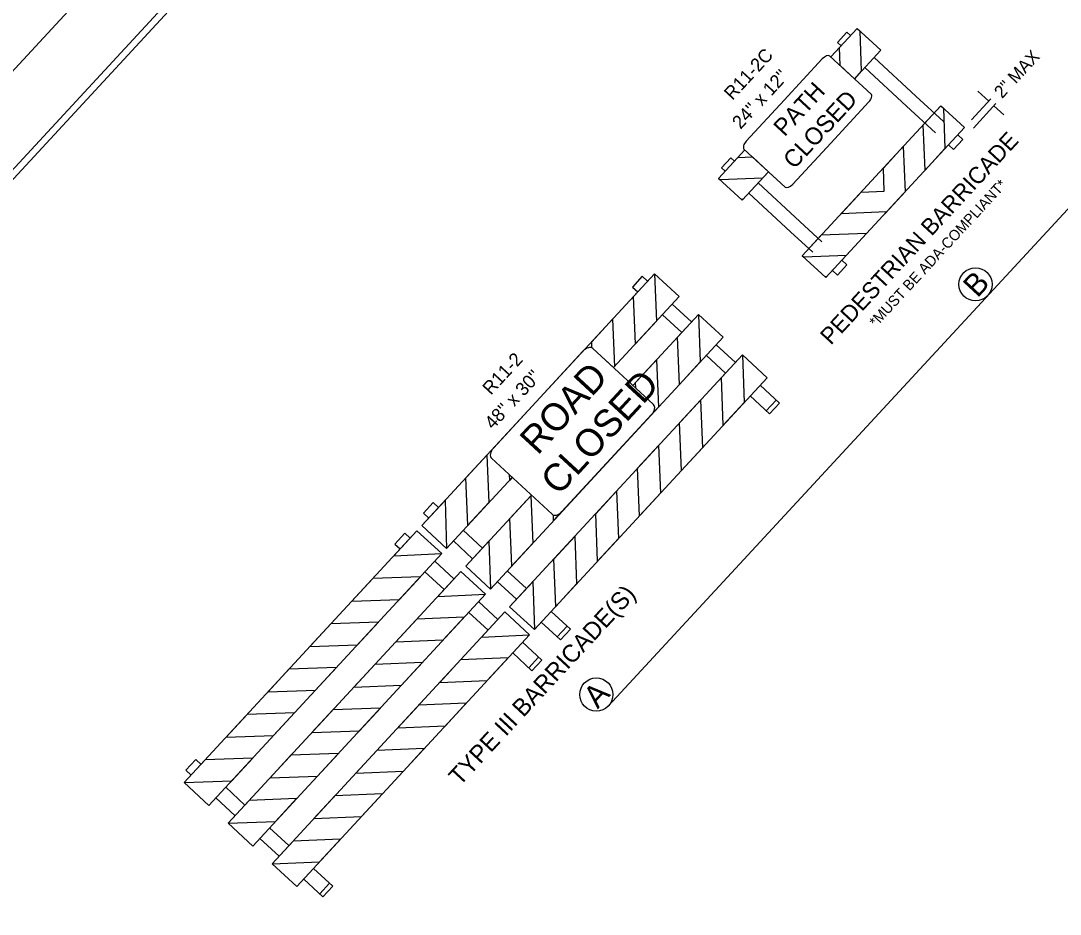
# Model space of a CAD drawing. Extents: x 1767460 to 1770129, y 996106 to 1001438.
# Drawn here: x 1768388.3 to 1768857.4, y 1000227.2 to 1000630.4 of the extents above; entities that cross this region are included whole.
import ezdxf

# ---------------------------------------------------------------- set-up
doc = ezdxf.new("R2010")
doc.units = 0
for name, color, linetype in [('_CIVIL_CONSTRUCTION', 7, 'Continuous'), ('E_NCDOT_Terrain_Model_Contour_Minor', 7, 'Continuous'), ('E_NCDOT_Terrain_Model_Points_Low', 7, 'Continuous'), ('E_NCDOT_Terrain_Model_Triangle_Vertices', 7, 'Continuous'), ('P_NCDOT_Terrain_Flow_Arrows', 7, 'Continuous'), ('P_NCDOT_Terrain_Points_High', 7, 'Continuous'), ('P_NCDOT_Terrain_Points_Low', 7, 'Continuous'), ('P_NCDOT_Terrain_Void', 7, 'Continuous'), ('P_RDY_Slope_Stake_Fill_Limits', 7, 'Continuous')]:
    doc.layers.add(name, color=color, linetype=linetype)

msp = doc.modelspace()

# ---------------------------------------------------------------- linework, layer by layer
at = {"layer": '_CIVIL_CONSTRUCTION'}
for centre in [(1768819.17, 1000511.43), (1768648.04, 1000326.3)]:
    msp.add_circle(centre, 7.5, dxfattribs=at)
at = {"layer": 'E_NCDOT_Terrain_Model_Contour_Minor'}
msp.add_lwpolyline([(1768744.05, 999038.07), (1770128.77, 1000536.12), (1769152.55, 1001438.49), (1767767.83, 999940.44)], close=True, dxfattribs=at)
at = {"layer": 'E_NCDOT_Terrain_Model_Points_Low'}
msp.add_lwpolyline([(1767804.38, 999935.46), (1769171.05, 1001413.98), (1770107.33, 1000548.53), (1768740.66, 999070.01)], close=True, dxfattribs=at)
at = {"layer": 'E_NCDOT_Terrain_Model_Triangle_Vertices'}
msp.add_lwpolyline([(1769163.02, 1001400.87), (1767932.52, 1000069.67), (1768864.37, 999208.32), (1770094.87, 1000539.52)], close=True, dxfattribs=at)
at = {"layer": 'P_NCDOT_Terrain_Flow_Arrows'}
for p, q in [((1768770.98, 1000593.73), (1768753.85, 1000575.19)), ((1768753.85, 1000575.19), (1768736.71, 1000556.65))]:
    msp.add_line(p, q, dxfattribs=at)
for points in [[(1768753.48, 1000614.44), (1768772.02, 1000597.31)], [(1768732.86, 1000594.59), (1768750, 1000613.13)], [(1768715.73, 1000576.05), (1768732.86, 1000594.59)], [(1768733.23, 1000555.34), (1768714.69, 1000572.47)]]:
    msp.add_lwpolyline(points, dxfattribs=at)
for centre, major_axis, start_param, end_param in [((1768751.22, 1000611.99), (2.26, 2.45), 0, 1.570796), ((1768769.76, 1000594.86), (-2.26, -2.45), 1.570796, 3.141593), ((1768716.95, 1000574.92), (-2.26, -2.45), 4.712162, 6.283185), ((1768735.49, 1000557.79), (-2.26, -2.45), 0, 1.570796)]:
    msp.add_ellipse(centre, major_axis=major_axis, ratio=0.5, start_param=start_param, end_param=end_param, dxfattribs=at)
at = {"layer": 'P_NCDOT_Terrain_Points_High'}
msp.add_lwpolyline([(1769163.02, 1001400.87), (1767932.52, 1000069.67), (1768864.37, 999208.32), (1769639.43, 1000046.81), (1769513.61, 1000163.11), (1769964.83, 1000651.25), (1769968.19, 1000656.62)], close=True, dxfattribs=at)
at = {"layer": 'P_NCDOT_Terrain_Points_Low'}
for p, q in [((1768765.78, 1000626.89), (1768753.91, 1000614.05)), ((1768761.16, 1000625.2), (1768756.91, 1000620.6)), ((1768757.83, 1000618.28), (1768765.78, 1000626.89)), ((1768762.81, 1000623.67), (1768761.11, 1000625.24)), ((1768776.39, 1000617.08), (1768765.78, 1000626.89)), ((1768758.56, 1000619.08), (1768756.91, 1000620.6)), ((1768758.15, 1000610.13), (1768757.83, 1000618.28)), ((1768764.52, 1000604.24), (1768776.39, 1000617.08)), ((1768792.3, 1000596.41), (1768773.42, 1000613.86)), ((1768788.06, 1000591.81), (1768769.17, 1000609.27)), ((1768804.7, 1000584.95), (1768792.3, 1000596.41)), ((1768817.4, 1000585.67), (1768826.1, 1000595.09)), ((1768820.28, 1000598.67), (1768825.2, 1000594.12)), ((1768803.55, 1000591.98), (1768741.01, 1000524.33)), ((1768801.1, 1000579.75), (1768788.06, 1000591.81)), ((1768795.59, 1000583.37), (1768803.55, 1000591.98)), ((1768814.16, 1000582.17), (1768803.55, 1000591.98)), ((1768818.23, 1000581.97), (1768828.4, 1000592.97)), ((1768827.5, 1000591.99), (1768831.95, 1000587.88)), ((1768751.63, 1000514.52), (1768814.16, 1000582.17)), ((1768796.4, 1000562.95), (1768795.59, 1000583.37)), ((1768813.48, 1000576.83), (1768809.24, 1000572.23)), ((1768813.48, 1000576.83), (1768811.19, 1000578.95)), ((1768715.12, 1000572.08), (1768703.25, 1000559.24)), ((1768777.59, 1000563.9), (1768786.59, 1000573.64)), ((1768786.59, 1000573.64), (1768787.39, 1000553.21)), ((1768805.4, 1000572.69), (1768796.4, 1000562.95)), ((1768809.24, 1000572.23), (1768806.94, 1000574.36)), ((1768711.8, 1000568.48), (1768703.25, 1000559.24)), ((1768708.81, 1000568.57), (1768704.57, 1000563.98)), ((1768710.47, 1000567.05), (1768708.81, 1000568.57)), ((1768718.71, 1000568.75), (1768711.8, 1000568.48)), ((1768706.22, 1000562.45), (1768704.57, 1000563.98)), ((1768713.86, 1000549.43), (1768725.73, 1000562.27)), ((1768778, 1000553.46), (1768777.59, 1000563.9)), ((1768703.25, 1000559.24), (1768713.86, 1000549.43)), ((1768739.96, 1000539.78), (1768721.08, 1000557.24)), ((1768735.72, 1000535.19), (1768716.83, 1000552.64)), ((1768758.56, 1000543.31), (1768767.57, 1000553.05)), ((1768767.57, 1000553.05), (1768778, 1000553.46)), ((1768787.39, 1000553.21), (1768778.39, 1000543.47)), ((1768714.21, 1000549.8), (1768713.48, 1000549.78)), ((1768713.86, 1000549.43), (1768714.21, 1000549.8)), ((1768778.99, 1000544.12), (1768758.56, 1000543.31)), ((1768749.88, 1000530.62), (1768739.96, 1000539.78)), ((1768745.69, 1000525.96), (1768735.72, 1000535.19)), ((1768769.98, 1000534.38), (1768749.56, 1000533.57)), ((1768760.98, 1000524.64), (1768769.98, 1000534.38)), ((1768749.56, 1000533.57), (1768741.01, 1000524.33)), ((1768741.01, 1000524.33), (1768751.63, 1000514.52)), ((1768761.14, 1000520.2), (1768756.9, 1000515.61)), ((1768761.14, 1000520.2), (1768758.85, 1000522.33)), ((1768751.98, 1000514.9), (1768751.25, 1000514.87)), ((1768751.63, 1000514.52), (1768751.98, 1000514.9)), ((1768756.9, 1000515.61), (1768754.6, 1000517.73))]:
    msp.add_line(p, q, dxfattribs=at)
for points in [[(1768765.78, 1000626.89), (1768766.92, 1000625.83), (1768767.64, 1000607.6)], [(1768767.64, 1000607.6), (1768764.52, 1000604.24), (1768758.15, 1000610.13)], [(1768803.55, 1000591.98), (1768804.68, 1000590.93), (1768805.4, 1000572.69)], [(1768723.21, 1000559.54), (1768725.73, 1000562.27), (1768718.71, 1000568.75)], [(1768703.25, 1000559.24), (1768703.74, 1000558.78), (1768723.21, 1000559.54)], [(1768741.01, 1000524.33), (1768741.51, 1000523.87), (1768760.98, 1000524.64)]]:
    msp.add_lwpolyline(points, dxfattribs=at)
at = {"layer": 'P_NCDOT_Terrain_Void'}
msp.add_line((1768653.55, 1000321.21), (1769189.14, 1000900.63), dxfattribs=at)
at = {"layer": 'P_RDY_Slope_Stake_Fill_Limits'}
for p, q in [((1768569.28, 1000402.55), (1768674.32, 1000516.19)), ((1768668.78, 1000515.04), (1768664.32, 1000510.22)), ((1768664.86, 1000505.96), (1768674.32, 1000516.19)), ((1768668.78, 1000515.04), (1768671.19, 1000512.81)), ((1768674.32, 1000516.19), (1768685.46, 1000505.89)), ((1768674.32, 1000516.19), (1768675.16, 1000494.75)), ((1768664.32, 1000510.22), (1768666.74, 1000507.99)), ((1768685.46, 1000505.89), (1768655.84, 1000473.84)), ((1768665.71, 1000484.52), (1768664.86, 1000505.96)), ((1768682.34, 1000502.51), (1768691.02, 1000494.49)), ((1768664.52, 1000465.82), (1768694.14, 1000497.86)), ((1768677.88, 1000497.69), (1768686.56, 1000489.66)), ((1768684.69, 1000487.64), (1768694.14, 1000497.86)), ((1768694.14, 1000497.86), (1768705.28, 1000487.57)), ((1768694.14, 1000497.86), (1768694.98, 1000476.42)), ((1768645.96, 1000485.51), (1768655.41, 1000495.74)), ((1768655.41, 1000495.74), (1768656.25, 1000474.3)), ((1768675.16, 1000494.75), (1768665.71, 1000484.52)), ((1768705.28, 1000487.57), (1768600.24, 1000373.93)), ((1768685.53, 1000466.2), (1768684.69, 1000487.64)), ((1768646.07, 1000482.76), (1768645.96, 1000485.51)), ((1768655.84, 1000473.84), (1768646.5, 1000482.47)), ((1768702.16, 1000484.19), (1768710.84, 1000476.16)), ((1768608.92, 1000365.91), (1768713.96, 1000479.54)), ((1768665.78, 1000467.19), (1768675.24, 1000477.41)), ((1768675.24, 1000477.41), (1768676.08, 1000455.97)), ((1768697.7, 1000479.37), (1768706.38, 1000471.34)), ((1768704.51, 1000469.32), (1768713.96, 1000479.54)), ((1768713.96, 1000479.54), (1768714.8, 1000458.1)), ((1768713.96, 1000479.54), (1768725.1, 1000469.24)), ((1768656.25, 1000474.3), (1768655.84, 1000473.84)), ((1768694.98, 1000476.42), (1768685.53, 1000466.2)), ((1768725.1, 1000469.24), (1768620.07, 1000355.61)), ((1768705.35, 1000447.88), (1768704.51, 1000469.32)), ((1768665.89, 1000464.55), (1768665.78, 1000467.19)), ((1768673.85, 1000457.19), (1768665.89, 1000464.55)), ((1768721.98, 1000465.87), (1768730.66, 1000457.84)), ((1768685.61, 1000448.87), (1768695.06, 1000459.09)), ((1768695.06, 1000459.09), (1768695.9, 1000437.65)), ((1768717.52, 1000461.04), (1768726.21, 1000453.02)), ((1768729.22, 1000459.18), (1768724.76, 1000454.36)), ((1768676.08, 1000455.97), (1768673, 1000452.65)), ((1768714.8, 1000458.1), (1768705.35, 1000447.88)), ((1768730.66, 1000457.84), (1768726.21, 1000453.02)), ((1768672.99, 1000452.63), (1768632.54, 1000408.87)), ((1768686.45, 1000427.43), (1768685.61, 1000448.87)), ((1768666.7, 1000428.42), (1768676.16, 1000438.64)), ((1768676.16, 1000438.64), (1768677, 1000417.2)), ((1768695.9, 1000437.65), (1768686.45, 1000427.43)), ((1768589.21, 1000424.11), (1768598.66, 1000434.34)), ((1768598.66, 1000434.34), (1768599.5, 1000412.9)), ((1768667.55, 1000406.98), (1768666.7, 1000428.42)), ((1768610.04, 1000424.3), (1768580.42, 1000392.26)), ((1768590.05, 1000402.67), (1768589.21, 1000424.11)), ((1768608.95, 1000423.12), (1768608.86, 1000425.39)), ((1768608.86, 1000425.39), (1768610.04, 1000424.3)), ((1768610.04, 1000424.3), (1768608.95, 1000423.12)), ((1768647.76, 1000407.92), (1768657.21, 1000418.14)), ((1768657.21, 1000418.14), (1768658.05, 1000396.7)), ((1768677, 1000417.2), (1768667.55, 1000406.98)), ((1768569.28, 1000402.55), (1768579.76, 1000413.89)), ((1768574.45, 1000412.98), (1768569.99, 1000408.16)), ((1768574.45, 1000412.98), (1768576.86, 1000410.75)), ((1768579.76, 1000413.89), (1768580.42, 1000392.26)), ((1768589.1, 1000384.23), (1768618.72, 1000416.28)), ((1768599.5, 1000412.9), (1768590.05, 1000402.67)), ((1768609.03, 1000405.79), (1768618.48, 1000416.02)), ((1768618.48, 1000416.02), (1768619.32, 1000394.58)), ((1768569.99, 1000408.16), (1768572.4, 1000405.93)), ((1768628.78, 1000404.8), (1768628.68, 1000407.29)), ((1768632.53, 1000408.87), (1768628.78, 1000404.8)), ((1768648.6, 1000386.48), (1768647.76, 1000407.92)), ((1768580.42, 1000392.26), (1768569.28, 1000402.55)), ((1768580.42, 1000392.26), (1768569.28, 1000402.55)), ((1768609.87, 1000384.35), (1768609.03, 1000405.79)), ((1768567.11, 1000400.21), (1768462.07, 1000286.57)), ((1768567.11, 1000400.21), (1768556.63, 1000388.87)), ((1768557.12, 1000394.24), (1768561.57, 1000399.06)), ((1768561.57, 1000399.06), (1768563.99, 1000396.83)), ((1768578.25, 1000389.91), (1768567.11, 1000400.21)), ((1768578.25, 1000389.91), (1768567.11, 1000400.21)), ((1768588, 1000400.46), (1768596.68, 1000392.43)), ((1768628.85, 1000387.47), (1768638.3, 1000397.69)), ((1768638.3, 1000397.69), (1768639.15, 1000376.25)), ((1768557.12, 1000394.24), (1768559.53, 1000392.01)), ((1768583.54, 1000395.63), (1768592.22, 1000387.61)), ((1768589.1, 1000384.23), (1768599.58, 1000395.57)), ((1768599.58, 1000395.57), (1768600.24, 1000373.93)), ((1768619.32, 1000394.58), (1768609.87, 1000384.35)), ((1768658.05, 1000396.7), (1768648.6, 1000386.48)), ((1768473.21, 1000276.27), (1768578.25, 1000389.91)), ((1768556.63, 1000388.87), (1768578.25, 1000389.91)), ((1768575.13, 1000386.53), (1768583.81, 1000378.51)), ((1768600.24, 1000373.93), (1768589.1, 1000384.23)), ((1768600.24, 1000373.93), (1768589.1, 1000384.23)), ((1768629.7, 1000366.03), (1768628.85, 1000387.47)), ((1768586.93, 1000381.88), (1768481.89, 1000268.25)), ((1768568.62, 1000379.49), (1768547.18, 1000378.65)), ((1768559.17, 1000369.26), (1768568.62, 1000379.49)), ((1768570.67, 1000381.71), (1768579.35, 1000373.68)), ((1768586.93, 1000381.88), (1768576.45, 1000370.55)), ((1768598.07, 1000371.58), (1768586.93, 1000381.88)), ((1768598.07, 1000371.58), (1768586.93, 1000381.88)), ((1768607.82, 1000382.13), (1768616.5, 1000374.11)), ((1768547.18, 1000378.65), (1768537.73, 1000368.42)), ((1768603.36, 1000377.31), (1768612.05, 1000369.28)), ((1768608.92, 1000365.91), (1768619.4, 1000377.24)), ((1768619.4, 1000377.24), (1768620.07, 1000355.61)), ((1768639.15, 1000376.25), (1768629.7, 1000366.03)), ((1768493.04, 1000257.95), (1768598.07, 1000371.58)), ((1768576.45, 1000370.55), (1768598.07, 1000371.58)), ((1768537.73, 1000368.42), (1768559.17, 1000369.26)), ((1768594.95, 1000368.21), (1768603.63, 1000360.18)), ((1768620.07, 1000355.61), (1768608.92, 1000365.91)), ((1768620.07, 1000355.61), (1768608.92, 1000365.91)), ((1768606.75, 1000363.56), (1768501.72, 1000249.93)), ((1768567, 1000360.32), (1768557.55, 1000350.1)), ((1768588.44, 1000361.17), (1768567, 1000360.32)), ((1768578.99, 1000350.94), (1768588.44, 1000361.17)), ((1768590.49, 1000363.38), (1768599.17, 1000355.36)), ((1768606.75, 1000363.56), (1768596.28, 1000352.22)), ((1768617.89, 1000353.26), (1768606.75, 1000363.56)), ((1768617.89, 1000353.26), (1768606.75, 1000363.56)), ((1768627.64, 1000363.81), (1768636.33, 1000355.78)), ((1768528.28, 1000358.2), (1768518.82, 1000347.97)), ((1768549.72, 1000359.04), (1768528.28, 1000358.2)), ((1768540.26, 1000348.81), (1768549.72, 1000359.04)), ((1768623.19, 1000358.99), (1768631.87, 1000350.96)), ((1768634.88, 1000357.12), (1768630.42, 1000352.3)), ((1768636.33, 1000355.78), (1768631.87, 1000350.96)), ((1768512.86, 1000239.63), (1768617.89, 1000353.26)), ((1768557.55, 1000350.1), (1768578.99, 1000350.94)), ((1768596.28, 1000352.22), (1768617.89, 1000353.26)), ((1768518.82, 1000347.97), (1768540.26, 1000348.81)), ((1768614.77, 1000349.88), (1768623.46, 1000341.86)), ((1768586.82, 1000342), (1768577.37, 1000331.77)), ((1768608.26, 1000342.84), (1768586.82, 1000342)), ((1768598.81, 1000332.62), (1768608.26, 1000342.84)), ((1768610.32, 1000345.06), (1768619, 1000337.04)), ((1768617.55, 1000338.37), (1768622.01, 1000343.2)), ((1768619, 1000337.04), (1768623.46, 1000341.86)), ((1768509.33, 1000337.7), (1768499.88, 1000327.47)), ((1768530.77, 1000338.54), (1768509.33, 1000337.7)), ((1768521.32, 1000328.32), (1768530.77, 1000338.54)), ((1768548.1, 1000339.87), (1768538.65, 1000329.65)), ((1768569.54, 1000340.72), (1768548.1, 1000339.87)), ((1768560.09, 1000330.49), (1768569.54, 1000340.72)), ((1768577.37, 1000331.77), (1768598.81, 1000332.62)), ((1768499.88, 1000327.47), (1768521.32, 1000328.32)), ((1768538.65, 1000329.65), (1768560.09, 1000330.49)), ((1768511.87, 1000318.09), (1768490.43, 1000317.25)), ((1768502.41, 1000307.87), (1768511.87, 1000318.09)), ((1768529.15, 1000319.37), (1768519.7, 1000309.15)), ((1768550.59, 1000320.22), (1768529.15, 1000319.37)), ((1768541.14, 1000309.99), (1768550.59, 1000320.22)), ((1768567.92, 1000321.55), (1768558.47, 1000311.32)), ((1768589.36, 1000322.39), (1768567.92, 1000321.55)), ((1768579.91, 1000312.17), (1768589.36, 1000322.39)), ((1768490.43, 1000317.25), (1768480.97, 1000307.02)), ((1768519.7, 1000309.15), (1768541.14, 1000309.99)), ((1768558.47, 1000311.32), (1768579.91, 1000312.17)), ((1768480.97, 1000307.02), (1768502.41, 1000307.87)), ((1768531.69, 1000299.77), (1768510.25, 1000298.92)), ((1768522.24, 1000289.54), (1768531.69, 1000299.77)), ((1768548.97, 1000301.05), (1768539.52, 1000290.83)), ((1768570.41, 1000301.89), (1768548.97, 1000301.05)), ((1768560.96, 1000291.67), (1768570.41, 1000301.89)), ((1768471.52, 1000296.8), (1768462.07, 1000286.57)), ((1768462.78, 1000292.18), (1768467.24, 1000297)), ((1768467.24, 1000297), (1768469.65, 1000294.77)), ((1768492.96, 1000297.64), (1768471.52, 1000296.8)), ((1768483.51, 1000287.42), (1768492.96, 1000297.64)), ((1768510.25, 1000298.92), (1768500.8, 1000288.7)), ((1768462.78, 1000292.18), (1768465.19, 1000289.95)), ((1768539.52, 1000290.83), (1768560.96, 1000291.67)), ((1768462.07, 1000286.57), (1768483.51, 1000287.42)), ((1768462.07, 1000286.57), (1768473.21, 1000276.27)), ((1768500.8, 1000288.7), (1768522.24, 1000289.54)), ((1768480.79, 1000284.47), (1768489.47, 1000276.45)), ((1768530.07, 1000280.6), (1768520.62, 1000270.38)), ((1768551.51, 1000281.44), (1768530.07, 1000280.6)), ((1768542.06, 1000271.22), (1768551.51, 1000281.44)), ((1768476.33, 1000279.65), (1768485.01, 1000271.63)), ((1768491.35, 1000278.47), (1768481.89, 1000268.25)), ((1768512.79, 1000279.32), (1768491.35, 1000278.47)), ((1768503.33, 1000269.09), (1768512.79, 1000279.32)), ((1768520.62, 1000270.38), (1768542.06, 1000271.22)), ((1768481.89, 1000268.25), (1768503.33, 1000269.09)), ((1768481.89, 1000268.25), (1768493.04, 1000257.95)), ((1768500.61, 1000266.15), (1768509.3, 1000258.13)), ((1768496.16, 1000261.33), (1768504.84, 1000253.3)), ((1768511.17, 1000260.15), (1768501.72, 1000249.93)), ((1768532.61, 1000260.99), (1768511.17, 1000260.15)), ((1768523.16, 1000250.77), (1768532.61, 1000260.99)), ((1768501.72, 1000249.93), (1768523.16, 1000250.77)), ((1768501.72, 1000249.93), (1768512.86, 1000239.63)), ((1768520.44, 1000247.83), (1768529.12, 1000239.8)), ((1768515.98, 1000243), (1768524.66, 1000234.98)), ((1768523.21, 1000236.32), (1768527.67, 1000241.14)), ((1768524.66, 1000234.98), (1768529.12, 1000239.8))]:
    msp.add_line(p, q, dxfattribs=at)
for points in [[(1768646.5, 1000482.47), (1768673.85, 1000457.19)], [(1768601.57, 1000437.49), (1768642.02, 1000481.25)], [(1768628.06, 1000407.65), (1768600.7, 1000432.93)]]:
    msp.add_lwpolyline(points, dxfattribs=at)
for centre, major_axis, start_param, end_param in [((1768643.83, 1000479.58), (2.67, 2.89), 0, 1.570796), ((1768643.83, 1000479.58), (2.67, 2.89), 6.283185, 6.491582), ((1768671.18, 1000454.3), (-2.67, -2.89), 1.570796, 3.141593), ((1768671.18, 1000454.3), (2.67, 2.89), 4.712389, 6.283185), ((1768603.38, 1000435.82), (-2.67, -2.89), 4.712162, 6.283185), ((1768630.73, 1000410.54), (-2.67, -2.89), 0, 1.571024), ((1768630.73, 1000410.54), (-2.67, -2.89), 0.287132, 1.570688)]:
    msp.add_ellipse(centre, major_axis=major_axis, ratio=0.625, start_param=start_param, end_param=end_param, dxfattribs=at)

# ---------------------------------------------------------------- texts
at = {"layer": '_CIVIL_CONSTRUCTION'}
for s, p in [('B', (1768820.04, 1000505.01)), ('A', (1768648.67, 1000319.61))]:
    msp.add_text(s, height=10, rotation=47.2512, dxfattribs=at).set_placement(p)
at = {"layer": 'P_NCDOT_Terrain_Flow_Arrows'}
for s, p in [('PATH', (1768732.99, 1000577.75)), ('CLOSED', (1768737.35, 1000563.05))]:
    msp.add_text(s, height=7.785, rotation=47.2512, dxfattribs=at).set_placement(p)
at = {"layer": 'P_NCDOT_Terrain_Points_Low'}
for s, height, p in [('2" MAX', 5.715, (1768831.17, 1000594.98)), ('PEDESTRIAN BARRICADE', 7.5076, (1768753.89, 1000483.7)), ('*MUST BE ADA-COMPLIANT*', 4.7627, (1768774.24, 1000491.79))]:
    msp.add_text(s, height=height, rotation=47.2512, dxfattribs=at).set_placement(p)
at = {"layer": 'P_RDY_Slope_Stake_Fill_Limits'}
for s, height, p in [('R11-2C', 6, (1768709.5, 1000594.19)), ("24'' x 12''", 6, (1768713.14, 1000581.13)), ('R11-2', 6, (1768600.47, 1000461.12)), ("48'' x 30''", 6, (1768601.41, 1000445.56)), ('ROAD', 12.369, (1768621.57, 1000433.98)), ('CLOSED', 12.369, (1768630.96, 1000415.69)), ('TYPE III BARRICADE(S)', 7.8816, (1768586.49, 1000284.72))]:
    msp.add_text(s, height=height, rotation=47.2512, dxfattribs=at).set_placement(p)

doc.saveas('drawing.dxf')
